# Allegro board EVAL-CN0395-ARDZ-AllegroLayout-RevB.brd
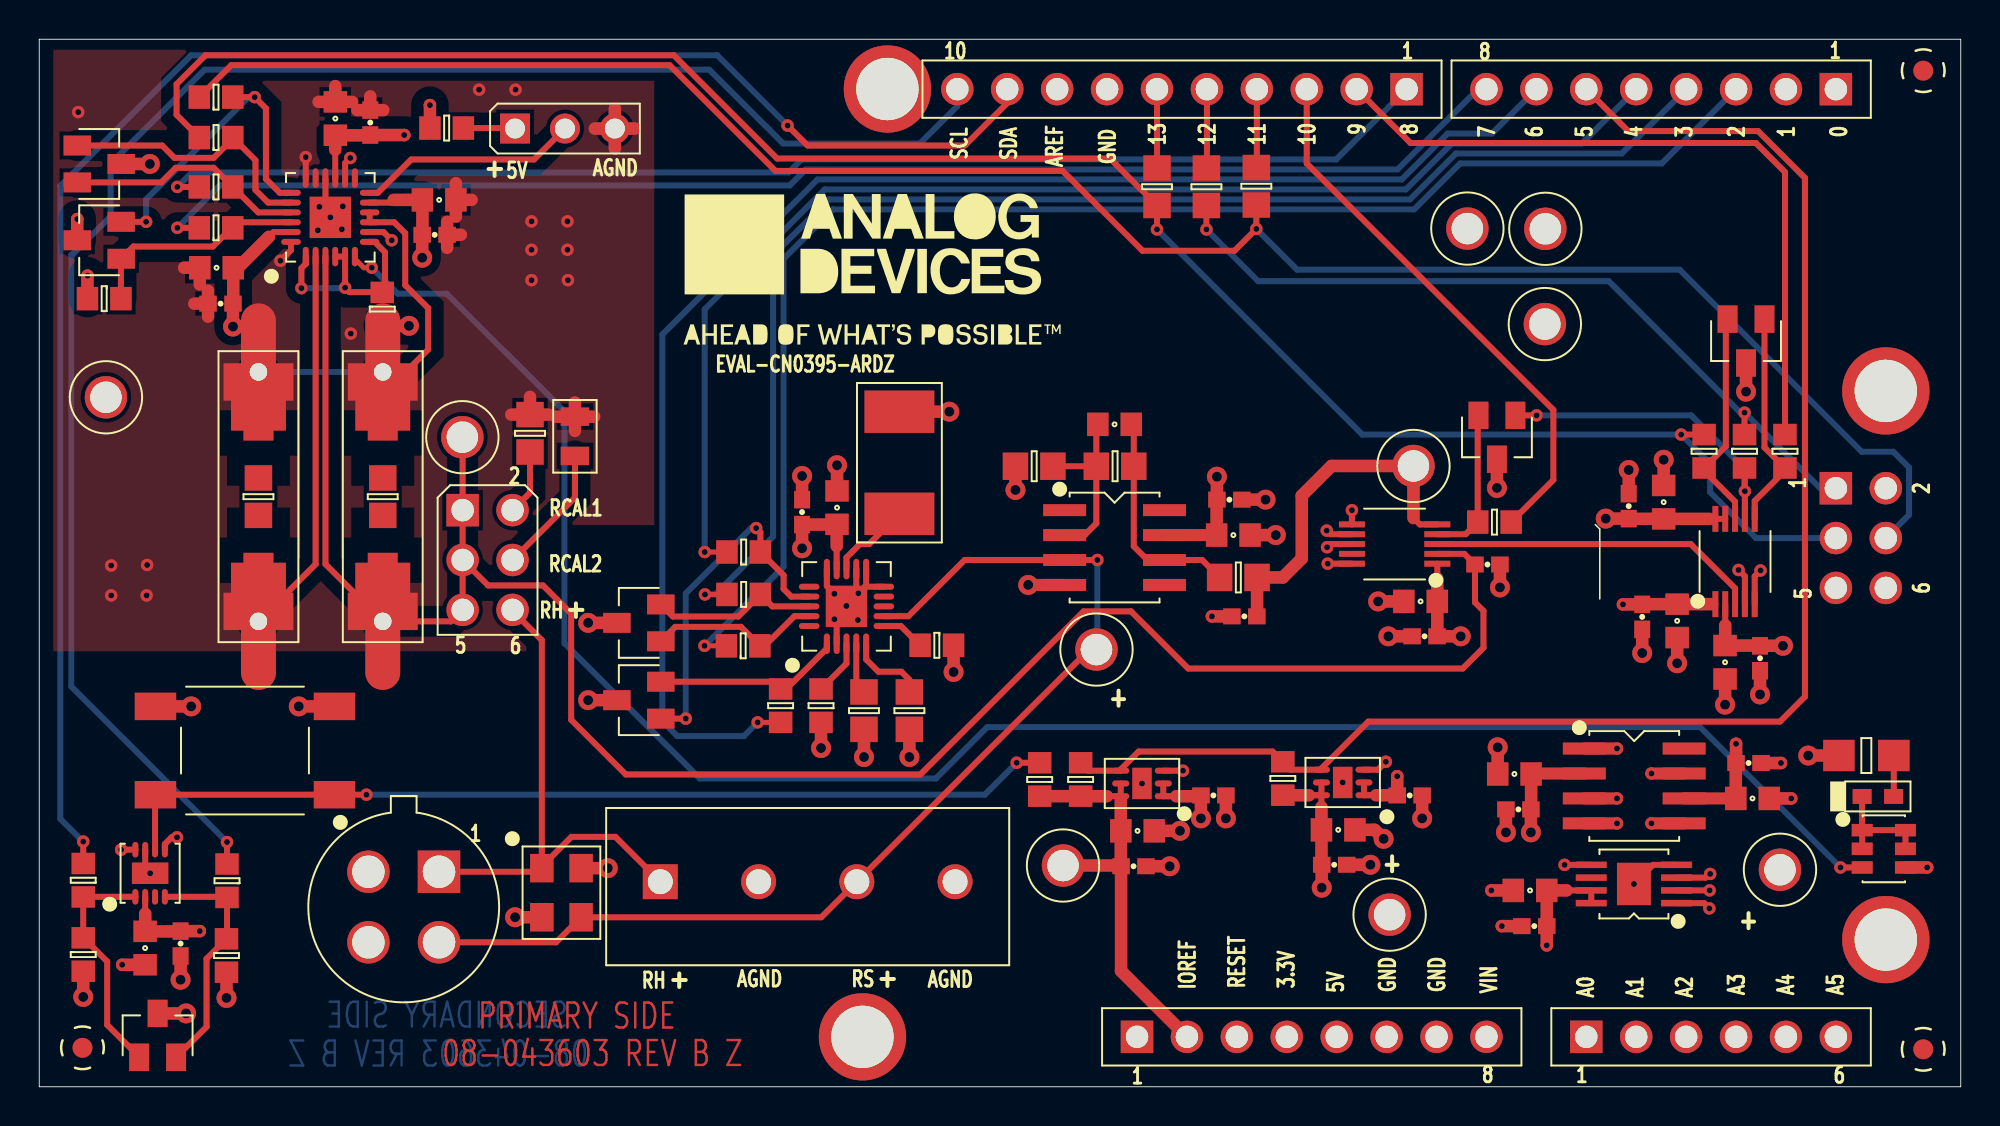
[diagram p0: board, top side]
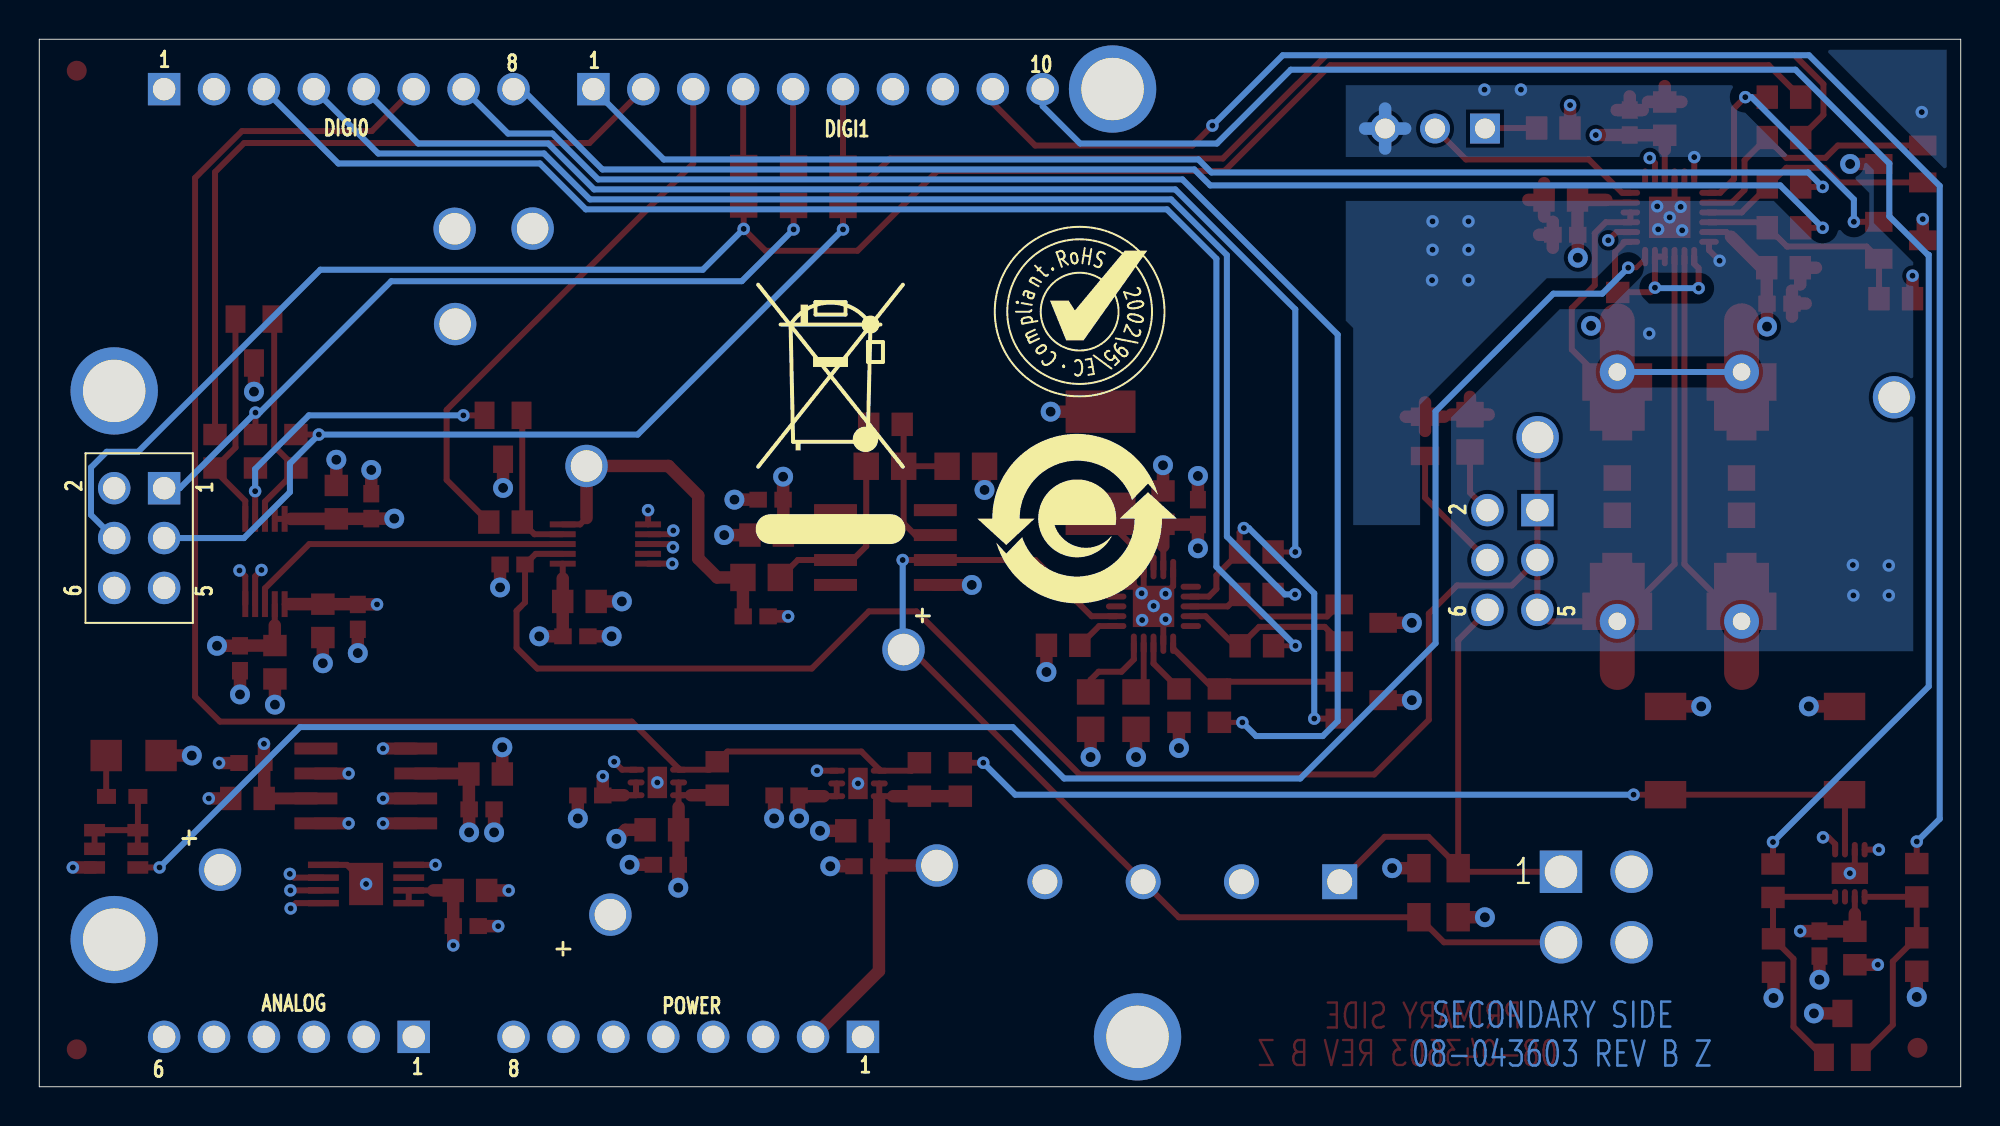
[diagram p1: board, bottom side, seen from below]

Outline 97.76 x 53.34 mm; copper layers: TOP, L2_GND, L3_PWR, BOTTOM. Coordinates in mm from the lower left corner of the outline.
Outline path: 0,53.34 0,0 97.76,0 97.76,53.34 0,53.34

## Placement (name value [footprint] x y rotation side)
A1  AD8628ARZ  [SO8]  54.71 27.46 270 top
AGND  RED  [CNLOOPTP]  76.63 43.69 0 top
C1  10uF  [C0402]  55.68 11.23 180 top
C2  10uF  [C0402]  65.89 11.3 180 top
C3  0.1uF  [C0603]  55.88 13.03 180 top
C4  0.1uF  [C0603]  66.09 13.08 180 top
C5  10uF  [C0402]  76.07 8.18 0 top
C6  0.1uF  [C0603]  75.85 9.99 0 top
C7  1uF  [C0402]  59.74 14.83 180 top
C8  1uF  [C0402]  69.73 14.83 180 top
C9  0.1uF  [C0603]  75.06 15.93 0 top
C10  1uF  [C0402]  75.26 14.12 0 top
C11  0.1uF  [C0603]  87.17 14.68 180 top
C12  1uF  [C0402]  86.97 16.48 180 top
C13  10uF  [C0402]  20.12 43.38 180 top
C14  0.1uF  [C0603]  20.35 45.16 180 top
C15  10uF  [C0402]  38.81 29.26 270 top
C16  0.1uF  [C0603]  40.59 29.49 270 top
C17  10uF  [C0402]  16.84 49.1 90 top
C18  0.1uF  [C0603]  15.06 49.3 90 top
C19  10uF  [C0402]  9.22 39.88 180 top
C20  0.1uF  [C0603]  9.02 41.71 180 top
C21  10uF  [C0402]  60.55 29.9 180 top
C22  0.1uF  [C0603]  60.76 28.09 180 top
C23  0.1uF  [C0603]  54.71 33.73 0 top
C24  1000pF  [C0402]  61.32 23.95 0 top
C25  220pF  [C0402]  73.69 26.59 180 top
C26  10uF  [C0402]  70.48 22.94 0 top
C27  0.1uF  [C0603]  70.28 24.71 0 top
C28  0.1uF  [C0603]  83.34 23.72 90 top
C29  1uF  [C0402]  81.56 23.93 90 top
C30  10uF  [C0402]  87.55 21.82 90 top
C31  0.1uF  [C0603]  85.78 21.62 90 top
C32  10uF  [C0402]  80.87 29.57 90 top
C33  0.1uF  [C0603]  82.65 29.77 90 top
C34  10uF  [C0402]  7.19 7.29 90 top
C35  0.1uF  [C0603]  5.38 7.06 90 top
D1  BAT54C  [SOT23]  3.05 43.1 90 top
D2  BAT54C  [SOT23]  30.51 19.69 90 top
D3  BAT54C  [SOT23]  3.05 46.99 270 top
D4  BAT54C  [SOT23]  74.17 33.07 180 top
D5  BAT54C  [SOT23]  86.84 37.97 180 top
D6  BAT54C  [SOT23]  6.02 2.62 0 top
D7  BAT54C  [SOT23]  30.51 23.62 90 top
DS1  APT1608SRCPRV  [LED0603]  93.55 14.78 0 top
IOREF  RED  [CNLOOPTP]  52.09 11.26 0 top
M1  VOC-MF1  [MVOC-MF1]  18.54 9.15 180 top
NOREF  -  []  97.76 0 90 top
NOREF#2  -  []  -124.84 228.42 0 top
NOREF#3  -  []  0 53.34 0 top
NOREF#4  -  []  0 0.03 0 top
NOREF#5  -  []  -234.98 -254 0 top
NOREF#6  -  []  201.93 49.48 0 top
NOREF#7  -  []  -0.03 53.37 270 top
NOREF#8  -  []  -234.98 -254 0 top
NOREF#9  -  [unnamed#2]  93.95 7.49 0 top
NOREF#10  -  []  0 0.03 0 top
NOREF#11  -  [unnamed#2]  93.95 35.43 0 top
NOREF#12  -  []  97.76 0 90 top
NOREF#13  -  [unnamed#2]  95.86 1.91 0 top
NOREF#14  -  []  21.13 1.66 0 top
NOREF#15  -  [unnamed#2]  41.88 2.54 0 top
NOREF#16  -  [unnamed#2]  43.15 50.81 0 top
NOREF#17  -  []  97.82 0 0 top
NOREF#18  -  []  97.76 53.34 180 top
NOREF#19  -  []  0 53.34 0 top
NOREF#20  -  [unnamed#2]  95.86 51.74 0 top
NOREF#21  -  []  146.02 209.55 0 top
NOREF#22  -  []  -234.98 -254 0 top
NOREF#23  -  []  0 0 0 top
NOREF#24  -  []  279.7 195.43 0 top
NOREF#25  -  [unnamed#2]  2.2 1.98 0 top
NOREF#26  -  []  165.15 243.21 0 top
NOREF#27  -  []  42.4 41.62 0 top
NOREF#28  -  []  48.23 44.53 180 bottom
NOREF#29  -  []  44.83 39.47 180 bottom
NOREF#30  -  []  44.96 28.93 180 bottom
P1  22-28-4033  [CNMOLEX22-28-4033]  24.21 48.79 0 top
P2  TSW-103-08-G-D  [CNSAMTEC2X3H330LD36]  21.54 29.36 270 top
P3  SSQ-103-03-G-D  [CNSAMTECSSQ-103-XX-X-D]  91.41 30.48 270 bottom
P4  SSQ-106-03-G-S  [CNSAMTECSSQ-106-XX-X-S]  78.71 2.54 0 top
P5  SSQ-108-03-G-S  [CNSAMTECSSQ-108-XX-X-S]  55.85 2.54 0 top
P6  SSQ-110-03-G-S  [CNSAMTECSSQ-110-XX-X-S]  69.57 50.8 180 top
P7  SSQ-108-03-G-S  [CNSAMTECSSQ-108-XX-X-S]  91.41 50.8 180 top
P8  CTB5000/4  [CN1X4H394]  31.6 10.44 0 top
Q1  IRLMS2002TRPBF  [SOT23_6-3]  93.85 12.12 270 top
R1  100K  [R0603]  52.98 15.65 90 top
R2  100K  [R0603]  63.27 15.7 90 top
R3  100  [R0603]  8.99 43.74 0 top
R4  100K  [R0603]  20.73 48.82 180 top
R5  100  [R0603]  8.99 45.82 0 top
R6  100  [R0603]  35.84 25.07 0 top
R7  100  [R0603]  8.99 48.34 0 top
R8  100  [R0603]  35.84 27.23 0 top
R9  100  [R0603]  8.99 50.39 0 top
R10  8.87K  [R0603]  39.78 19.41 90 top
R11  10K  [R0603]  3.3 40.13 180 top
R12  39.2K  [R0805]  41.96 19.15 90 top
R13  110K  [R0805]  44.27 19.15 90 top
R14  2.74MEG  [R0603]  45.67 22.48 180 top
R15  100K  [R0603]  17.45 39.6 270 top
R16  33MEG  [R2512H31]  43.76 31.78 270 top
R17  8.25  [R0805]  11.15 30.05 90 top
R17_SPACER  TBD_SPACER_500_D37  [R_SPACER_500_D37]  11.15 23.7 90 top
R18  5K  [R0805]  50.62 31.6 0 top
R19  8.25  [R0805]  17.48 30.05 270 top
R19_SPACER  TBD_SPACER_500_D37  [R_SPACER_500_D37]  17.48 23.7 90 top
R20  5K  [R0805]  54.74 31.6 0 top
R21  20  [R0805]  61.01 25.93 0 top
R22  71.5  [R0805]  24.97 33.27 90 top
R23  10  [R0805H20]  27.25 33.12 90 top
R24  100  [R0603]  74.04 28.75 180 top
R25  100  [R0603]  86.77 32.36 270 top
R26  37.4  [R1206]  92.96 16.87 180 top
R27  100  [R0603]  84.71 32.36 270 top
R28  100  [R0603]  88.82 32.36 270 top
R29  10K  [R0603]  2.24 6.73 270 top
R30  10K  [R0603]  9.53 6.68 270 top
R31  100  [R0603]  2.24 10.52 90 top
R32  100  [R0603]  9.55 10.49 90 top
R33  0  [R0805]  61.93 45.85 90 top
R34  0  [R0805]  59.39 45.83 90 top
R35  0  [R0805]  56.87 45.83 90 top
R36  10K  [R0603]  50.9 15.65 90 top
R37  100  [R0603]  35.81 22.45 0 top
R38  100  [R0603]  37.72 19.41 90 top
RS+  RED  [CNLOOPTP]  53.79 22.26 0 top
S2  FSM2JSMA  [SWSMSQ236H185]  10.46 17.12 90 top
TP2  RED  [CNLOOPTP]  3.39 35.11 270 top
U1  ADN8810ACPZ  [QFN24_4X4_PAD2_1X2_1]  14.81 44.27 0 top
U2  -  [TGS8100]  26.57 9.88 270 top
U3  ADP196ACPZN  [DFN6_2X2_PAD1_6X1]  56.11 15.44 90 top
U4  ADP196ACPZN  [DFN6_2X2_PAD1_6X1]  66.32 15.49 90 top
U5  ADP124ARHZ-2.5  [MSOP8_PAD2_16X1_73]  81.14 10.32 90 top
U6  ADR4540BRZ  [SO8]  81.15 15.32 270 top
U7  ADG758BCPZ  [QFN20_4X4_PAD2_1X2_1]  41.07 24.46 0 top
U8  ADG884BRMZ  [RM10]  68.96 27.64 90 top
U9  AD7988-1BRMZ  [RM10]  86.28 26.75 0 top
U10  SHT30-DIS-B2.5KS  [DFN8_2_5X2_5_PAD1_8X1_1]  5.64 10.87 0 top
UNK4.096V  RED  [CNLOOPTP]  76.61 38.84 0 top
UNK5V  RED  [CNLOOPTP]  72.66 43.7 0 top
UNK+2.5V  RED  [CNLOOPTP]  88.57 11.05 0 top
UNK+5V_ARD  RED  [CNLOOPTP]  68.71 8.76 0 top
VH  RED  [CNLOOPTP]  21.53 33.08 270 top
VRS  RED  [CNLOOPTP]  69.92 31.61 0 top

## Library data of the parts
A1 = AD8628: Tolerance: N/A; User Part Number: UPN; alternate symbols: (); part number: AD8628_SM-AD8628ARZ,E018085,SO8; tolerance: N/A
AGND IOREF RS+ TP2 UNK4.096V UNK5V UNK+2.5V UNK+5V_ARD VH VRS = CNTP1P: User Part Number: UPN; Tolerance: N/A; alternate symbols: (); part number: CNTP1P_TH-RED,E000947,CNLOOPTP; tolerance: N/A
C1 C2 C5 C13 C15 C17 C19 C21 C26 C30 C32 C34 = CAP: Tolerance: 20; User Part Number: UPN; alternate symbols: (); part number: CAP_SM-10UF,6.3V,20,E020966,C0402; tolerance: 20
C3 C4 C6 C9 C11 C14 C16 C18 C20 C22 C23 C27 C28 C31 C33 C35 = CAP: Tolerance: 10; User Part Number: UPN; alternate symbols: (); part number: CAP_SM-0.1UF,16V,10,E015036,C0603; tolerance: 10
C7 C8 C10 C12 C29 = CAP: Tolerance: 10; User Part Number: UPN; alternate symbols: (); part number: CAP_SM-1UF,6.3V,10,E007449,C0402; tolerance: 10
C24 = CAP: Tolerance: 5; User Part Number: UPN; alternate symbols: (); part number: CAP_SM-1000PF,50V,5,E012419,C0402; tolerance: 5
C25 = CAP: Tolerance: 5; User Part Number: UPN; alternate symbols: (); part number: CAP_SM-220PF,50V,5,E012615,C0402; tolerance: 5
D1-D7 = DIOSCHOTTKY3P_V10: User Part Number: UPN; Tolerance: N/A; alternate symbols: (); part number: DIOSCHOTTKY3P_V10_SM-BAT54C,30V,N/A,E021001,SOT23; tolerance: N/A
DS1 = DIOLED: Tolerance: N/A; User Part Number: UPN; alternate symbols: (); part number: DIOLED_SM-APT1608SRCPRV,N/A,N/A,E018073,LED0603; tolerance: N/A
M1 = MOD_VOC_MF1: User Part Number: UPN; Tolerance: N/A; alternate symbols: MVOC-MF1_SKTLD55; part number: MOD_VOC_MF1_TH-VOC-MF1,E026030,MVOC-MF1; tolerance: N/A
P1 = CN3P: User Part Number: UPN; Tolerance: N/A; alternate symbols: (); part number: CN3P_TH-22-28-4033,E005952,CNMOLEX22-28-4033; tolerance: N/A
P2 = CN6P_ODD_EVEN: Tolerance: N/A; User Part Number: UPN; alternate symbols: (); part number: CN6P_ODD_EVEN_TH-TSW-103-08-G-D,E006383,CNSAMTEC2X3H330LD36; tolerance: N/A
P3 = CN6P: User Part Number: UPN; Tolerance: N/A; alternate symbols: (); part number: CN6P_TH-SSQ-103-03-G-D,E020488,CNSAMTECSSQ-103-XX-X-D; tolerance: N/A
P4 = CN6P: User Part Number: UPN; Tolerance: N/A; alternate symbols: (); part number: CN6P_TH-SSQ-106-03-G-S,E020477,CNSAMTECSSQ-106-XX-X-S; tolerance: N/A
P5 P7 = CN8P_A: User Part Number: UPN; Tolerance: N/A; alternate symbols: (); part number: CN8P_A_TH-SSQ-108-03-G-S,E020478,CNSAMTECSSQ-108-XX-X-S; tolerance: N/A
P6 = CN10P: User Part Number: UPN; Tolerance: N/A; alternate symbols: (); part number: CN10P_TH-SSQ-110-03-G-S,E020479,CNSAMTECSSQ-110-XX-X-S; tolerance: N/A
P8 = CN4P: Tolerance: N/A; User Part Number: UPN; alternate symbols: (); part number: CN4P_TH-CTB5000/4,E015992,CN1X4H394; tolerance: N/A
Q1 = TRANNMOSFET_V17: User Part Number: UPN; Tolerance: N/A; alternate symbols: (); part number: TRANNMOSFET_V17_SM-IRLMS2002TRPBF,E018862,SOT23_6-3; tolerance: N/A
R1 R2 R4 R15 = RES: Tolerance: 1; User Part Number: UPN; alternate symbols: (); part number: RES_SM-100K,E010279,1/10W,1,R0603; tolerance: 1
R3 R5-R9 R24 R25 R27 R28 R31 R32 R37 R38 = RES: Tolerance: 1; User Part Number: UPN; alternate symbols: (); part number: RES_SM-100,E003668,1/10W,1,R0603; tolerance: 1
R10 = RES: Tolerance: 0.1; User Part Number: UPN; alternate symbols: (); part number: RES_SM-8.87K,E021125,1/10W,0.1,R0603; tolerance: 0.1
R11 R36 = RES: Tolerance: 1; User Part Number: UPN; alternate symbols: (); part number: RES_SM-10K,E003671,1/10W,1,R0603; tolerance: 1
R12 = RES: Tolerance: 0.1; User Part Number: UPN; alternate symbols: (); part number: RES_SM-39.2K,E020454,1/8W,0.1,R0805; tolerance: 0.1
R13 = RES: Tolerance: 0.1; User Part Number: UPN; alternate symbols: (); part number: RES_SM-110K,E010949,1/8W,0.1,R0805; tolerance: 0.1
R14 = RES: Tolerance: 1; User Part Number: UPN; alternate symbols: (); part number: RES_SM-2.74MEG,E028525,1/10W,1,R0603; tolerance: 1
R16 = RES: User Part Number: UPN; Tolerance: 1; alternate symbols: (); part number: RES_SM-33MEG,E028402,1W,1,R2512H31; tolerance: 1
R17 R19 = RES: Tolerance: 0.1; User Part Number: UPN; alternate symbols: (); part number: RES_SM-8.25,E026824,1/10W,0.1,R0805; tolerance: 0.1
R17_SPACER R19_SPACER = RES: User Part Number: UPN; alternate symbols: (); part number: RES_TH-TBD_SPACER_500_D37,E018836,TBD_SPACER_500_D37,TBD_SPACER_500_D37,R_SPACER_500_D37
R18 R20 = RES: Tolerance: 0.1; User Part Number: UPN; alternate symbols: (); part number: RES_SM-5K,E014315,1/5W,0.1,R0805; tolerance: 0.1
R21 = RES: Tolerance: 1; User Part Number: UPN; alternate symbols: (); part number: RES_SM-20,E003563,1/8W,1,R0805; tolerance: 1
R22 = RES: Tolerance: 0.1; User Part Number: UPN; alternate symbols: (); part number: RES_SM-71.5,E026034,1/4W,0.1,R0805; tolerance: 0.1
R23 = RES: Tolerance: 0.1; User Part Number: UPN; alternate symbols: (); part number: RES_SM-10,E026825,1W,0.1,R0805H20; tolerance: 0.1
R26 = RES: Tolerance: 1; User Part Number: UPN; alternate symbols: (); part number: RES_SM-37.4,E003269,1/4W,1,R1206; tolerance: 1
R29 R30 = RES: Tolerance: 1; User Part Number: UPN; alternate symbols: (); part number: RES_SM-10K,E015126,1/4W,1,R0603; tolerance: 1
R33-R35 = RES: Tolerance: N/A; User Part Number: UPN; alternate symbols: (); part number: RES_SM-0,E004152,1/10W,N/A,R0805; tolerance: N/A
S2 = SWSPST4PIN_B: User Part Number: UPN; Tolerance: N/A; alternate symbols: (); part number: SWSPST4PIN_B_SM-FSM2JSMA,E016530,SWSMSQ236H185; tolerance: N/A
U1 = ADN8810: Tolerance: N/A; User Part Number: UPN; alternate symbols: (); part number: ADN8810_SM-ADN8810ACPZ,E025853,QFN24_4X4_PAD2_1X2_1; tolerance: N/A
U2 = ICTGS8100: User Part Number: UPN; Tolerance: N/A; alternate symbols: (); part number: ICTGS8100_SM-TGS8100,E025852,TGS8100; tolerance: N/A
U3 U4 = ADP196_V2: User Part Number: UPN; Tolerance: N/A; alternate symbols: (); part number: ADP196_V2_SM-ADP196ACPZN,E020439,DFN6_2X2_PAD1_6X1; tolerance: N/A
U5 = ADP124: Tolerance: N/A; User Part Number: UPN; alternate symbols: (); part number: ADP124_SM-ADP124ARHZ-2.5,E021632,MSOP8_PAD2_16X1_73; tolerance: N/A
U6 = ADR45XX: Tolerance: N/A; User Part Number: UPN; alternate symbols: (); part number: ADR45XX_SM-ADR4540BRZ,E017544,SO8; tolerance: N/A
U7 = ADG758: User Part Number: UPN; Tolerance: N/A; alternate symbols: (); part number: ADG758_SM-ADG758BCPZ,E021726,QFN20_4X4_PAD2_1X2_1; tolerance: N/A
U8 = ADG884_V2: Tolerance: N/A; User Part Number: UPN; alternate symbols: (); part number: ADG884_V2_SM-ADG884BRMZ,E014585,RM10; tolerance: N/A
U9 = AD7988: Tolerance: N/A; User Part Number: UPN; alternate symbols: (); part number: AD7988_SM-AD7988-1BRMZ,E024959,RM10; tolerance: N/A
U10 = ICSHT3X: User Part Number: UPN; Tolerance: N/A; alternate symbols: (); part number: ICSHT3X_SM-SHT30-DIS-B2.5KS,E025987,DFN8_2_5X2_5_PAD1_8X1_1; tolerance: N/A

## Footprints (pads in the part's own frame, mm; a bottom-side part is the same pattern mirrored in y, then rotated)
C0402
  rect 0.889x0.813 smd: 1(-0.635,0) 2(0.635,0)
C0603
  rect 1.092x1.194 smd: 1(-0.851,0) 2(0.851,0)
CN1X4H394
  rect 1.778x1.778 hole 1.27: 1(0,0)
  round 1.778 hole 1.27: 2(5,0) 3(10,0) 4(15,0)
CNLOOPTP
  round 2.159 hole 1.6: 1(0,0)
CNMOLEX22-28-4033
  rect 1.524x1.524 hole 1.016: 1(0,0)
  round 1.524 hole 1.016: 2(2.54,0) 3(5.08,0)
CNSAMTEC2X3H330LD36
  rect 1.651x1.651 hole 1.143: 1(0,0)
  round 1.651 hole 1.143: 2(0,2.54) 3(2.54,0) 4(2.54,2.54) 5(5.08,0) 6(5.08,2.54)
CNSAMTECSSQ-103-XX-X-D
  rect 1.651x1.651 hole 1.143: 1(0,0)
  round 1.651 hole 1.143: 2(0,-2.54) 3(2.54,0) 4(2.54,-2.54) 5(5.08,0) 6(5.08,-2.54)
CNSAMTECSSQ-106-XX-X-S
  rect 1.651x1.651 hole 1.143: 1(0,0)
  round 1.651 hole 1.143: 2(2.54,0) 3(5.08,0) 4(7.62,0) 5(10.16,0) 6(12.7,0)
CNSAMTECSSQ-108-XX-X-S
  rect 1.651x1.651 hole 1.143: 1(0,0)
  round 1.651 hole 1.143: 2(2.54,0) 3(5.08,0) 4(7.62,0) 5(10.16,0) 6(12.7,0) 7(15.24,0) 8(17.78,0)
CNSAMTECSSQ-110-XX-X-S
  rect 1.651x1.651 hole 1.143: 1(0,0)
  round 1.651 hole 1.143: 2(2.54,0) 3(5.08,0) 4(7.62,0) 5(10.16,0) 6(12.7,0) 7(15.24,0) 8(17.78,0) 9(20.32,0) 10(22.86,0)
DFN6_2X2_PAD1_6X1
  oval 0.305x0.864 smd: 1(-0.65,-1.082) 2(0,-1.082) 3(0.65,-1.082) 4(0.65,1.082) 5(0,1.082) 6(-0.65,1.082)
  rect 1.6x0.991 smd: PAD(0,0)
DFN8_2_5X2_5_PAD1_8X1_1
  oval 0.305x0.787 smd: 1(-0.75,-1.2) 2(-0.25,-1.2) 3(0.25,-1.2) 4(0.75,-1.2) 5(0.75,1.2) 6(0.25,1.2) 7(-0.25,1.2) 8(-0.75,1.2)
  rect 1.854x1.092 smd: PAD(0,0)
LED0603
  rect 0.965x0.762 smd: A(0.8,0) C(-0.8,0)
MSOP8_PAD2_16X1_73
  rect 0.33x1.575 smd: 1(-0.975,-2.171) 2(-0.325,-2.171) 3(0.325,-2.171) 4(0.975,-2.171) 5(0.975,2.171) 6(0.325,2.171) 7(-0.325,2.171) 8(-0.975,2.171)
  rect 2.159x1.727 smd: PAD(0,0)
MVOC-MF1
  rect 2.159x2.159 hole 1.651: 1(-1.796,-1.796)
  round 2.159 hole 1.651: 2(-1.796,1.796) 3(1.796,1.796) 4(1.796,-1.796)
QFN20_4X4_PAD2_1X2_1
  oval 0.305x1.041 smd: 1(-1,-1.9) 2(-0.5,-1.9) 3(0,-1.9) 4(0.5,-1.9) 5(1,-1.9) 11(1,1.9) 12(0.5,1.9) 13(0,1.9) 14(-0.5,1.9) 15(-1,1.9)
  oval 1.041x0.305 smd: 6(1.9,-1) 7(1.9,-0.5) 8(1.9,0) 9(1.9,0.5) 10(1.9,1) 16(-1.9,1) 17(-1.9,0.5) 18(-1.9,0) 19(-1.9,-0.5) 20(-1.9,-1)
  rect 2.108x2.108 smd: PAD(0,0)
QFN24_4X4_PAD2_1X2_1
  oval 0.305x0.991 smd: 1(-1.25,-2) 2(-0.75,-2) 3(-0.25,-2) 4(0.25,-2) 5(0.75,-2) 6(1.25,-2) 13(1.25,2) 14(0.75,2) 15(0.25,2) 16(-0.25,2) 17(-0.75,2) 18(-1.25,2)
  oval 0.991x0.305 smd: 7(2,-1.25) 8(2,-0.75) 9(2,-0.25) 10(2,0.25) 11(2,0.75) 12(2,1.25) 19(-2,1.25) 20(-2,0.75) 21(-2,0.25) 22(-2,-0.25) 23(-2,-0.75) 24(-2,-1.25)
  rect 2.108x2.108 smd: PAD(0,0)
R0603
  rect 1.092x1.194 smd: 1(-0.851,0) 2(0.851,0)
R0805
  rect 1.295x1.397 smd: 1(-0.953,0) 2(0.953,0)
R0805H20
  rect 0.94x1.448 smd: 1(-1,0) 2(1,0)
R1206
  rect 1.6x1.6 smd: 1(-1.397,0) 2(1.397,0)
R2512H31
  rect 2.159x3.556 smd: 1(-2.6,0) 2(2.6,0)
R_SPACER_500_D37
  custom 0.889x0.889 hole 0.94: 1(0,0) 2(12.7,0)
RM10
  rect 0.305x1.321 smd: 1(-1,-2.171) 2(-0.5,-2.171) 3(0,-2.171) 4(0.5,-2.171) 5(1,-2.171) 6(1,2.171) 7(0.5,2.171) 8(0,2.171) 9(-0.5,2.171) 10(-1,2.171)
SO8
  rect 0.61x2.184 smd: 1(-1.905,-2.54) 2(-0.635,-2.54) 3(0.635,-2.54) 4(1.905,-2.54) 5(1.905,2.54) 6(0.635,2.54) 7(-0.635,2.54) 8(-1.905,2.54)
SOT23
  rect 1.016x1.397 smd: 1(-0.94,-1.118) 2(0.94,-1.118) 3(0,1.118)
SOT23_6-3
  rect 0.635x1.067 smd: 1(-0.95,-1.1) 2(0,-1.1) 3(0.95,-1.1) 4(0.95,1.1) 5(0,1.1) 6(-0.95,1.1)
SWSMSQ236H185
  rect 1.397x2.108 smd: 1(-2.248,-4.554) 2(-2.248,4.554) 3(2.248,-4.554) 4(2.248,4.554)
TGS8100
  rect 1.448x1.194 smd: 1(-1.25,-1) 2(1.25,-1) 3(1.25,1) 4(-1.25,1)
unnamed#2
  round 4.445 hole 3.175 unplated: (0,0)

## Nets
+2.5V: C30.2(N2) C31.2(N2) R26.2(N2) U5.1(VOUT1) U5.2(VOUT2) U5.3(VOUT_SENSE) U9.2(VDD) UNK+2.5V.1
+4.096V: C11.2(N2) C12.2(N2) C28.2(N2) C29.2(N2) R10.1(N1) R12.1(N1) R13.1(N1) R14.1(N1) R16.1(N1) U1.14(VREF) U6.6(VOUT) U9.1(REF) UNK4.096V.1
+5V: A1.7(V+) C5.2(N2) C6.2(N2) C8.2(N2) C9.2(N2) C10.2(N2) C13.2(N2) C14.2(N2) C15.2(N2) C16.2(N2) C17.1(N1) C18.1(N1) C21.2(N2) C22.2(N2) C26.2(N2) C27.2(N2) D2.3(N3) D4.3(N3) D5.3(N3) D7.3(N3) R4.2(N2) U1.8(PVDD_1) U1.11(PVDD_2) U1.15(AVDD) U4.1(VOUT1) U4.2(VOUT2) U5.5(EN) U5.7(VIN1) U5.8(VIN2) U6.2(VIN) U7.14(VDD) U8.1(VDD) UNK5V.1
+5V_ARD: C2.2(N2) C4.2(N2) P5.5(N5) R2.1(N1) U4.5(VIN2) U4.6(VIN1) UNK+5V_ARD.1
AGND: A1.4(V-) AGND.1(N1) C1.1(N1) C2.1(N1) C3.1(N1) C4.1(N1) C5.1(N1) C6.1(N1) C7.1(N1) C8.1(N1) C9.1(N1) C10.1(N1) C11.1(N1) C12.1(N1) C13.1(N1) C14.1(N1) C15.1(N1) C16.1(N1) C17.2(N2) C18.2(N2) C19.2(N2) C20.2(N2) C21.1(N1) C22.1(N1) C24.1(N1) C25.1(N1) C26.1(N1) C27.1(N1) C28.1(N1) C29.1(N1) C30.1(N1) C31.1(N1) C32.2(N2) C33.2(N2) C34.1(N1) C35.1(N1) M1.3(HE_2) M1.4(DE_2) P1.3(N3) P3.6(N6) P5.6(N6) P5.7(N7) P6.7(N7) P8.2(N2) P8.4(N4) Q1.4(S) R18.1(N1) R22.2(N2) R23.2(N2) S2.3(N3) S2.4(N4) U1.16(AVSS) U1.18(DVSS) U1.24(DGND) U1.PAD U2.2(SENSOR_ELECTRODE(-)) U2.4(HEATER2) U3.3(GND) U3.PAD U4.3(GND) U4.PAD U5.4(GND) U5.PAD(EP) U6.1(NC1) U6.3(NC2) U6.4(GND) U6.5(NC3) U6.7(NC4) U7.2(VSS) U7.10(S8) U7.11(S7) U7.12(S6) U7.15(GND) U7.PAD U8.6(GND) U8.7(S2B) U8.8(IN2) U8.10(S2A) U9.4(IN-) U9.5(GND) U10.7(R) U10.8(VSS) U10.PAD
A0: P7.3(N3) R37.1(N1)
A1: P7.4(N4) R6.1(N1)
A2: P7.5(N5) R8.1(N1)
CNV: P6.2(N2) R28.1(N1)
CS_N_ARD: P6.1(N1) R5.1(N1)
FAULT: Q1.3(G) U1.6(FAULT)
IN1: P6.3(N3) R24.1(N1)
IO5: P7.6(N6) R1.2(N2) R2.2(N2) U3.4(EN) U4.4(EN)
IO6: P7.7(N7) R38.1(N1)
IO7: P7.8(N8) R3.1(N1)
IOREF: C1.2(N2) C3.2(N2) IOREF.1(N1) P5.2(N2) R1.1(N1) R36.1(N1) U3.5(VIN2) U3.6(VIN1)
MISO_ARD: P3.1(N1) R25.1(N1) R34.1(N1)
MOSI_ARD: P3.4(N4) R9.1(N1) R33.1(N1)
RESET: D1.1(N1) R3.2(N2) R11.1(N1) U1.22(RESET*)
RH+: M1.1(HE_1) P2.6(N6) P8.1(N1) U2.1(HEATER1)
RS+: A1.3(+IN) M1.2(DE_1) P8.3(N3) RS+.1(N1) U2.3(SENSOR_ELECTRODE(+)) U7.7(D)
RSN: R17.1(N1) R17_SPACER.1(N1) U1.2(RSN)
SCL_ARD: P6.10(N10) R32.2(N2)
SCLK_ARD: P3.3(N3) R7.1(N1) R27.1(N1) R35.1(N1)
SDA_ARD: P6.9(N9) R31.2(N2)
SDO: D4.1(N1) R25.2(N2) U9.7(SDO)
UNNAMED_4_AD8628_I22_: A1.2(-IN) C23.1(N1) R18.2(N2) R20.1(N1)
UNNAMED_4_AD8628_I22_OUT: A1.6(OUT) C23.2(N2) R20.2(N2) R21.1(N1)
UNNAMED_4_ADG758_I12_A1: D7.2(N2) R6.2(N2) U7.18(A1)
UNNAMED_4_ADG758_I12_A2: D2.1(N1) R8.2(N2) U7.17(A2)
UNNAMED_4_ADG758_I12_EN: D2.2(N2) R38.2(N2) U7.1(EN)
UNNAMED_4_ADG758_I12_S1: R10.2(N2) U7.3(S1)
UNNAMED_4_ADG758_I12_S2: R12.2(N2) U7.4(S2)
UNNAMED_4_ADG758_I12_S3: R13.2(N2) U7.5(S3)
UNNAMED_4_ADG758_I12_S4: R14.2(N2) U7.6(S4)
UNNAMED_4_ADG758_I12_S5: R16.2(N2) U7.13(S5)
UNNAMED_4_ADN8810_I1_ADDR0: R15.1(N1) U1.1(ADDR2) U1.4(ADDR1) U1.5(ADDR0) U1.7(SB*)
UNNAMED_4_ADN8810_I1_CS: D3.2(N2) R5.2(N2) U1.21(CS*)
UNNAMED_4_ADN8810_I1_ENCOMP: P1.2(N2) U1.12(ENCOMP)
UNNAMED_4_ADN8810_I1_IOUT1: R17.2(N2) R17_SPACER.2(N2) R19.1(N1) R19_SPACER.2(N2) U1.9(IOUT_1) U1.10(IOUT_2)
UNNAMED_4_ADN8810_I1_SCLK: D3.1(N1) R7.2(N2) U1.20(SCLK)
UNNAMED_4_ADN8810_I1_SDI: D1.2(N2) R9.2(N2) U1.19(SDI)
UNNAMED_4_CN3P_I51_N1: P1.1(N1) R4.1(N1)
UNNAMED_4_CN6PODDEVEN_I59_N2: P2.2(N2) R22.1(N1)
UNNAMED_4_CN6PODDEVEN_I59_N4: P2.4(N4) R23.1(N1)
UNNAMED_4_DIOSCHOTTKY3PV10_I80_: D7.1(N1) R37.2(N2) U7.19(A0)
UNNAMED_5_AD7988_I3_CNV: D5.1(N1) R28.2(N2) U9.6(CNV)
UNNAMED_5_AD7988_I3_IN: U8.3(D1) U9.3(IN+)
UNNAMED_5_AD7988_I3_SCK: D5.2(N2) R27.2(N2) U9.8(SCK)
UNNAMED_5_DIOLED_I70_N: DS1.C(N) Q1.1(D1) Q1.2(D2) Q1.5(D3) Q1.6(D4)
UNNAMED_5_DIOLED_I70_P: DS1.A(P) R26.1(N1)
UNNAMED_5_DIOSCHOTTKY3PV10_I6_1: D6.2(N2) R30.1(N1) R32.1(N1) U10.4(SCL)
UNNAMED_5_DIOSCHOTTKY3PV10_I60_: D4.2(N2) R24.2(N2) U8.4(IN1)
UNNAMED_5_DIOSCHOTTKY3PV10_I64_: D6.1(N1) R29.1(N1) R31.1(N1) U10.1(SDA)
UNNAMED_5_RES_I68_N2: R36.2(N2) S2.1(N1) S2.2(N2) U10.6(RESET_N)
UNNAMED_7_CN10P_I1_N4: P6.4(N4) R33.2(N2)
UNNAMED_7_CN10P_I1_N5: P6.5(N5) R34.2(N2)
UNNAMED_7_CN10P_I1_N6: P6.6(N6) R35.2(N2)
VH: C25.2(N2) P2.1(N1) P2.3(N3) P2.5(N5) R19.2(N2) R19_SPACER.1(N1) U1.3(FB) U8.2(S1A) VH.1(N1)
VIO: C7.2(N2) C19.1(N1) C20.1(N1) C32.1(N1) C33.1(N1) C34.2(N2) C35.2(N2) D1.3(N3) D3.3(N3) D6.3(N3) R11.2(N2) R15.2(N2) R29.2(N2) R30.2(N2) TP2.1(N1) U1.23(DVDD) U3.1(VOUT1) U3.2(VOUT2) U9.9(SDI) U9.10(VIO) U10.2(ADDR) U10.5(VDD)
VRS: C24.2(N2) R21.2(N2) U8.5(S1B) VRS.1(N1)

Pads without a net: A1 1 5 8; P3 2 5; P4 1 2 3 4 5 6; P5 1 3 4 8; P6 8; P7 1 2; U1 13 17; U5 6; U6 8; U7 8 9 16 20; U8 9; U10 3

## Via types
v1: diameter 0.635, hole 0.305, TOP to BOTTOM, 94 vias
v2: diameter 1.016, hole 0.508, TOP to BOTTOM, 53 vias

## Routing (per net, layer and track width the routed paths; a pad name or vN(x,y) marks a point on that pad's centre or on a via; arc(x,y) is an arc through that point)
+2.5V: length 17.2
  TOP w0.305: U5.3 84.79,10.65 84.81,10.67 84.85,10.67 v1(85.02,10.84) ; v1(84.98,9.08) 84.71,9.35 U5.1 ; U5.2 v1(84.99,10) ; 85.78,23.5 U9.2
  TOP w0.635: v2(88.72,22.45) C30.2 87.54,22.47 C31.2 85.78,22.47 85.78,23.5 ; R26.2 v2(90,16.87)
  L3_PWR w0.635: UNK+2.5V.1 88.57,12.38 ; UNK+2.5V.1 88.57,9.71 ; UNK+2.5V.1 87.24,11.05 ; UNK+2.5V.1 89.9,11.05
+4.096V: length 24.6
  TOP w0.305: U1.14 15.56,47.03 v1(15.82,47.29) ; 85.06,24.58 U9.1
  TOP w0.61: U6.6 C11.2
  TOP w0.635: C11.2 86.32,16.47 86.33,16.48 v1(86.33,17.46) ; R10.1 v2(39.78,17.25) ; R16.1 v2(46.3,34.38) ; 85.06,24.58 C28.2 81.57,24.57 C29.2 v1(80.58,24.56) ; R14.1 v2(46.52,21.12) ; R13.1 v2(44.27,16.79) ; R12.1 v2(41.96,16.79)
  L3_PWR w0.635: UNK4.096V.1 76.61,40.17 ; UNK4.096V.1 77.94,38.84 ; UNK4.096V.1 76.61,37.5 ; UNK4.096V.1 75.27,38.84
+5V: length 56.9
  TOP w0.305: U5.5 v1(77.61,11.3) ; 15.06,47.71 U1.15 ; 68.02,14.84 U4.1 U4.2 ; 18.03,45.16 17.89,45.02 U1.11 ; U5.8 U5.7 77.72,10 ; U1.8 17.51,43.52 v1(17.93,43.1) ; 71.13,25.88 U8.1 ; U7.14 40.57,27.53
  TOP w0.61: A1.7 C22.2 ; C9.2 75.93,15.95 U6.2
  TOP w0.635: v2(72.33,22.94) C26.2 71.13,22.95 C27.2 71.13,24.71 71.13,25.88 ; C22.2 59.91,29.88 C21.2 v2(59.92,31.06) ; 15.06,47.71 15.06,48.45 C18.1 16.83,48.45 C17.1 v1(18.57,48.46) ; R4.2 v1(19.88,49.99) ; C9.2 75.91,14.14 C10.2 v2(75.9,12.95) ; D2.3 v2(27.93,19.69) ; v1(76.7,7.2) C5.2 C6.2 76.71,10 77.72,10 ; 68.02,14.84 69.08,14.84 C8.2 v1(69.09,15.81) ; D5.3 v2(86.84,35.39) ; 40.58,28.63 C16.2 ; 40.58,28.63 C15.2 v2(38.81,27.42) ; 40.58,28.63 40.57,28.62 40.57,27.53 ; D7.3 v2(27.93,23.62) ; D4.3 v2(74.17,30.49) ; v2(19.48,42.21) C13.2 19.49,43.4 C14.2 18.03,45.16
  L3_PWR w0.635: 71.33,43.7 UNK5V.1 ; UNK5V.1 72.66,45.03 ; UNK5V.1 74,43.7 ; UNK5V.1 72.66,42.37
+5V_ARD: length 17
  TOP w0.305: U4.5 U4.6 ; U4.6 65.24,14.24 ; U4.6 64.6,14.84
  TOP w0.635: v2(65.25,10.13) C2.2 65.24,11.32 C4.2 65.24,13.08 65.24,14.24 ; 64.6,14.84 63.27,14.84 R2.1
  L3_PWR w0.635: UNK+5V_ARD.1 70.04,8.76 ; UNK+5V_ARD.1 68.71,10.1 ; UNK+5V_ARD.1 67.37,8.76 ; UNK+5V_ARD.1 68.71,7.43 ; P5.5 67.09,2.54 ; P5.5 66.01,3.62 ; P5.5 64.93,2.54 ; P5.5 66.01,1.46
AGND: length 152
  TOP w0.305: U7.12 41.57,25.23 v1(41.68,25.13) 42.01,25.46 ; U1.24 12.81,42.6 v1(12.27,42.06) ; U10.8 v1(4.16,12.07) ; U9.5 87.28,25.99 v1(87.58,26.29) ; v1(65.52,27.47) 65.69,27.64 U8.8 ; v1(81.14,10.32) 82.11,11.3 U5.4 ; U10.7 5.39,11.12 v1(5.64,10.87) ; 42.01,25.46 U7.10 ; 42.01,25.46 42.07,25.52 U7.11 ; U4.3 68.11,16.14 v1(68.52,16.55) ; U7.15 40.07,25.49 40.46,25.11 v1(40.46,25.1) ; U8.6 v1(66.79,29.36) ; v1(65.51,28.32) 65.69,28.14 U8.7 ; U8.10 v1(65.56,26.64) ; v1(14.25,44.81) 14.56,45.11 U1.16 ; v1(40.46,23.81) 40.57,23.69 U7.2 ; U3.3 v1(58.19,16.09) ; U1.18 v1(13.56,47.34) ; U9.4 86.78,25.99 v1(86.46,26.31)
  TOP w0.61: A1.4 v2(50.32,25.55) ; U6.1 v1(80.28,17.22) ; U6.3 v1(80.28,14.68) ; U6.7 v1(82.03,15.95) ; U6.5 v1(82.03,13.41) ; U6.4 v1(80.28,13.41)
  TOP w0.635: 29.29,47.78 P1.3 ; P1.3 30.3,48.79 ; P1.3 29.29,49.81 ; P1.3 28.27,48.79 ; C27.1 v2(68.12,24.71) ; R23.2 27.25,34.85 ; R23.2 28.23,34.12 ; R23.2 27.25,33.4 ; R23.2 26.28,34.12 ; C26.1 v2(68.64,22.94) ; C13.1 20.75,44.04 ; C13.1 21.45,43.38 ; C13.1 20.75,42.72 ; C33.2 v2(82.65,31.93) ; C17.2 16.84,50.43 ; C17.2 17.5,49.73 ; C17.2 16.18,49.73 ; C2.1 v2(67.73,11.3) ; 24.02,34.23 R22.2 ; R22.2 25.92,34.23 ; R22.2 24.97,35.13 ; C16.1 v2(40.59,31.65) ; C19.2 8.59,40.54 ; C19.2 7.89,39.88 ; C19.2 8.59,39.22 ; C6.1 v1(73.88,9.99) ; 8.17,40.86 C20.2 7.37,41.71 ; 21.2,44.31 C14.1 ; C14.1 22,45.16 ; C14.1 21.2,46.01 ; S2.4 v2(7.73,19.37) ; C15.1 v2(38.81,31.1) ; C25.1 v2(74.32,25.43) ; C4.1 67.95,13.08 v2(68.4,12.62) ; C29.1 v2(81.56,22.09) ; R18.1 v2(49.67,30.39) ; C9.1 v2(74.21,17.28) ; C5.1 v1(74.42,8.18) ; C11.1 v1(89.14,14.68) ; C22.1 v2(62.92,28.09) ; C18.2 15.06,50.95 ; C18.2 14.21,50.15 ; C18.2 15.91,50.15 ; C7.1 v2(60.38,13.67) ; C34.1 v2(7.19,5.45) ; C10.1 v2(74.63,12.95) ; C1.1 v2(57.52,11.23) ; C8.1 v2(70.36,13.67) ; U2.4 v2(28.93,11.13) ; C32.2 v2(80.87,31.41) ; U2.2 v2(24.21,8.63) ; C28.1 v2(83.34,21.56) ; C31.1 v2(85.78,19.46) ; C24.1 v1(59.66,23.95) ; C12.1 v1(88.62,16.48) ; S2.3 v2(13.2,19.37) ; 61.19,29.9 v2(62.4,29.9) ; C35.1 v1(4.22,6.21) ; C3.1 v2(58.04,13.03) ; C30.1 v2(87.55,19.98) ; Q1.4 v1(96.06,11.17)
  L2_GND w0.635: P8.4 47.74,10.44 ; P8.4 45.45,10.44 ; P8.4 46.6,9.3 ; P8.4 46.6,11.58 ; P5.6 69.63,2.54 ; P5.6 67.47,2.54 ; P5.6 68.55,1.46 ; P5.6 68.55,3.62 ; 54.33,49.72 P6.7 ; P6.7 54.33,51.88 ; P6.7 55.41,50.8 ; P6.7 53.25,50.8 ; 71.09,1.46 P5.7 ; P5.7 72.17,2.54 ; P5.7 71.09,3.62 ; P5.7 70.01,2.54 ; 92.87,25.4 93.95,25.4 ; 93.95,25.4 95.03,25.4 ; 93.95,25.4 93.95,24.32 ; 93.95,25.4 93.95,26.48 ; P1.3 29.29,49.81 ; P1.3 28.27,48.79 ; P1.3 30.3,48.79 ; P1.3 29.29,47.78 ; M1.4 16.75,12.28 ; M1.4 16.75,9.61 ; M1.4 15.41,10.95 ; M1.4 18.08,10.95 ; P8.2 36.6,11.58 ; P8.2 35.45,10.44 ; P8.2 37.74,10.44 ; P8.2 36.6,9.3 ; 76.63,42.35 AGND.1 ; AGND.1 75.3,43.69 ; AGND.1 77.97,43.69 ; AGND.1 76.63,45.02 ; 15.41,7.35 M1.3 ; M1.3 16.75,8.69 ; M1.3 18.08,7.35 ; M1.3 16.75,6.02
  BOTTOM w0.635: P1.3 30.3,48.79 ; P1.3 28.27,48.79 ; P1.3 29.29,47.78 ; P1.3 29.29,49.81
  vias: v1(1.98,49.63) v1(3.66,26.54) v1(3.66,25.02) v1(5.49,26.57) v1(5.46,25.02) v1(14.17,43.61) v1(14.81,44.27) v1(15.39,43.66) v1(15.44,44.83) v1(15.85,38.35) v1(22.38,50.77) v1(24.23,50.77) v1(25.04,44.07) v1(25.04,42.62) v1(25.04,41.07) v1(26.87,44.07) v1(26.87,42.62) v1(26.9,41.07) v1(41.07,24.48) v1(41.65,23.77) v1(56.11,15.44) v1(66.32,15.49)
A0: length 74.5
  TOP w0.254: R37.1 v1(33.85,22.45)
  BOTTOM w0.305: v1(33.85,22.45) 37.87,26.48 37.87,42.16 40.39,44.68 69.96,44.68 72.29,47.02 82.55,47.02 86.33,50.8
A1: length 70.1
  TOP w0.254: R6.1 v1(33.87,25.07)
  BOTTOM w0.305: 83.79,50.8 80.52,47.52 72.08,47.52 69.75,45.19 40.18,45.19 37.34,42.35 37.34,28.02 34.39,25.07 v1(33.87,25.07)
A2: length 65.5
  TOP w0.254: R8.1 v1(33.86,27.23)
  BOTTOM w0.305: P7.5 78.49,48.03 71.87,48.03 69.53,45.69 39.96,45.69 33.86,39.59 v1(33.86,27.23)
CNV: length 36.9
  TOP w0.305: P6.2 69.77,48.06 87.34,48.06 88.82,46.58 R28.1
CS_N_ARD: length 65.7
  TOP w0.305: R5.1 v1(7.02,45.82)
  BOTTOM w0.305: v1(7.02,45.82) 7.76,46.56 38.13,46.56 38.79,47.22 65.99,47.22 P6.1
FAULT: length 98.7
  TOP w0.254: U1.6 16.06,42.16 16.51,41.71 v1(16.92,41.71)
  TOP w0.305: Q1.3 v1(91.65,11.17)
  BOTTOM w0.305: v1(16.92,41.71) 18.24,40.39 20.73,40.39 26.72,34.39 26.72,22.58 33.6,15.7 45.62,15.7 48.23,18.31 84.5,18.31 v1(91.65,11.17)
IN1: length 28.1
  TOP w0.305: R24.1 77.04,30.9 77.04,34.47 64.49,47.02 P6.3
IO5: length 78.8
  TOP w0.305: 78.71,50.8 80.85,48.67 87.45,48.67 89.84,46.28 89.84,19.86 88.57,18.59 67.62,18.59 65.24,16.21 U4.4 63.68,16.14 R2.2 62.75,17.07 55.94,17.07 55.03,16.16 U3.4 53.39,16.09 R1.2
IO6: length 76
  TOP w0.254: R38.1 v1(36.55,18.55)
  BOTTOM w0.305: v1(36.55,18.55) 35.85,17.86 32.46,17.86 31.7,18.62 31.7,38.3 39.6,46.2 69.32,46.2 71.66,48.54 73.91,48.54 P7.7
IO7: length 70.7
  TOP w0.305: R3.1 v1(7.02,43.74)
  BOTTOM w0.305: v1(7.02,43.74) 9.18,45.9 38.18,45.9 39,46.71 69.11,46.71 73.2,50.8 P7.8
IOREF: length 21.4
  TOP w0.305: 54.32,14.79 U3.6 ; U3.6 U3.5 ; U3.6 55.03,14.79 55.03,14.55
  TOP w0.635: R36.1 R1.1 52.99,14.79 54.32,14.79 ; IOREF.1 55,11.26 55.03,11.24 ; 55.03,11.24 C3.2 55.03,14.55 ; 55.03,11.24 C1.2 55.04,5.89 P5.2
MISO_ARD: length 39.8
  TOP w0.305: R25.1 v1(86.77,34.33) ; R34.1 v1(59.39,43.66)
  BOTTOM w0.305: P3.1 90.61,30.48 v1(86.77,34.33) 86.55,34.33 79.86,41.02 62.02,41.02 v1(59.39,43.66)
MOSI_ARD: length 102.4
  TOP w0.305: R33.1 v1(61.93,43.68) 60.81,42.57 56.13,42.57 52.07,46.63 37.46,46.63 32.07,52.02 9.77,52.02 R9.1
  BOTTOM w0.305: v1(61.93,43.68) 64,41.61 83.46,41.61 92.74,32.33 94.34,32.33 95.14,31.53 95.14,29.12 P3.4
RESET: length 11.4
  TOP w0.305: R11.1 4.15,42.15 D1.1 4.79,42.79 8.83,42.79 9.79,43.74 R3.2 10.13,44.02 U1.22
RH+: length 26.7
  TOP w0.305: 25.57,11.22 U2.1 25.38,10.95 M1.1 ; 25.57,11.22 25.57,22.74 24.08,24.23 P2.6 ; 25.57,11.22 27.08,12.73 29.31,12.73 P8.1
RS+: length 56.3
  TOP w0.305: M1.2 26.29,7.35 U2.3 39.79,8.63 P8.3 53.42,22.26 RS+.1 ; v1(53.84,26.82) A1.3 47.08,26.82 44.22,23.96 U7.7
  BOTTOM w0.305: RS+.1 53.84,22.31 v1(53.84,26.82)
RSN: length 19.8
  TOP w0.305: R17_SPACER.1 14.06,26.61 U1.2
SCL_ARD: length 88.1
  TOP w0.305: R32.2 v1(9.55,12.46)
  BOTTOM w0.305: P6.10 46.71,49.94 44.81,48.03 37.85,48.03 34.09,51.79 8.41,51.79 3.63,47.02 3.63,44.32 1.68,42.37 1.63,42.37 1.63,20.38 v1(9.55,12.46)
SCLK_ARD: length 101.2
  TOP w0.305: R27.1 v1(83.54,33.21) ; R7.1 6.99,49.49 6.99,51.05 8.46,52.53 32.28,52.53 37.54,47.27 54.48,47.27 R35.1 v1(56.87,43.66)
  BOTTOM w0.305: v1(56.87,43.66) 67.32,33.21 v1(83.54,33.21) 85.01,31.74 85.01,30.28 87.35,27.94 P3.3
SDA_ARD: length 89.4
  TOP w0.305: P6.9 49.25,50.09 47.09,47.93 39.09,47.93 v1(38.07,48.95) ; R31.2 v1(2.24,12.48)
  BOTTOM w0.305: v1(2.24,12.48) 2.22,12.48 1.07,13.64 1.07,45.87 7.72,52.53 34.49,52.53 v1(38.07,48.95)
SDO: length 16.5
  TOP w0.305: R25.2 86.77,30.35 v1(86.78,30.33) U9.7 ; D4.1 v1(76.19,34.19)
  BOTTOM w0.305: v1(76.19,34.19) 84.05,34.19 86.78,31.45 v1(86.78,30.33)
UNNAMED_4_AD8628_I22_: length 9.1
  TOP w0.305: A1.2 53.19,28.09 53.78,28.69 R20.1 ; C23.1 53.78,33.66 R20.1 ; R18.2 R20.1
UNNAMED_4_AD8628_I22_OUT: length 11.3
  TOP w0.305: C23.2 55.69,33.6 R20.2 55.69,27.52 56.39,26.82 A1.6 59.17,26.82 R21.1
UNNAMED_4_ADG758_I12_A1: length 8.5
  TOP w0.305: D7.2 32.24,23.95 35.57,23.95 R6.2 37.3,24.46 U7.18
UNNAMED_4_ADG758_I12_A2: length 17.7
  TOP w0.305: D2.1 v1(32.89,18.75) ; U7.17 38.26,24.96 37.87,25.35 37.87,26.05 R8.2 36.69,28.23 v1(36.47,28.45)
  BOTTOM w0.305: v1(32.89,18.75) 32.89,25.12 36.22,28.45 v1(36.47,28.45)
UNNAMED_4_ADG758_I12_EN: length 9.7
  TOP w0.305: D2.2 37.35,20.62 R38.2 38.01,20.26 40.07,22.32 U7.1
UNNAMED_4_ADG758_I12_S1: length 2.8
  TOP w0.305: R10.2 41.07,21.55 U7.3
UNNAMED_4_ADG758_I12_S2: length 2.6
  TOP w0.305: R12.2 41.57,20.49 U7.4
UNNAMED_4_ADG758_I12_S3: length 4.1
  TOP w0.305: R13.2 44.27,20.73 43.87,21.13 42.7,21.13 42.07,21.76 U7.5
UNNAMED_4_ADG758_I12_S4: length 2.3
  TOP w0.305: R14.2 43.84,23.46 U7.6
UNNAMED_4_ADG758_I12_S5: length 4.2
  TOP w0.305: U7.13 41.07,26.95 41.76,27.64 42.22,27.64 R16.2
UNNAMED_4_ADN8810_I1_ADDR0: length 11.1
  TOP w0.305: U1.7 17.06,43.02 17.59,42.49 17.59,40.59 R15.1 17.44,40.46 15.79,40.46 v1(15.56,40.69) U1.5 U1.4 ; U1.1 13.56,41.9 13.34,41.68 v1(13.34,40.67)
  BOTTOM w0.305: v1(13.34,40.67) 15.53,40.67 v1(15.56,40.69)
UNNAMED_4_ADN8810_I1_CS: length 12.1
  TOP w0.305: U1.21 11.14,44.52 R5.2 8.87,46.79 6.94,46.79 6.2,46.05 D3.2
UNNAMED_4_ADN8810_I1_ENCOMP: length 11.3
  TOP w0.305: P1.2 25.17,47.22 18.92,47.22 17.23,45.52 U1.12
UNNAMED_4_ADN8810_I1_IOUT1: length 18.1
  TOP w0.305: U1.10 U1.9 18.06,44.02 18.62,43.46 18.62,40.82 19.79,39.65 19.79,37.54 18.64,36.4 R19_SPACER.2
  BOTTOM w0.305: R17_SPACER.2 R19_SPACER.2
UNNAMED_4_ADN8810_I1_SCLK: length 13.9
  TOP w0.305: D3.1 6.25,47.93 6.88,47.3 8.87,47.3 9.84,48.27 R7.2 11,47.18 11,45.67 11.65,45.02 U1.20
UNNAMED_4_ADN8810_I1_SDI: length 17.2
  TOP w0.305: R9.2 v1(10.96,50.39) 11.53,49.82 11.53,46.23 12.24,45.52 U1.19 ; D1.2 v1(5.44,44.04)
  BOTTOM w0.305: v1(5.44,44.04) 5.44,45.19 10.64,50.39 v1(10.96,50.39)
UNNAMED_4_CN3P_I51_N1: length 2.6
  TOP w0.305: P1.1 24.18,48.82 R4.1
UNNAMED_4_CN6PODDEVEN_I59_N2: length 3.3
  TOP w0.305: P2.2 24.97,30.25 R22.1
UNNAMED_4_CN6PODDEVEN_I59_N4: length 6.6
  TOP w0.305: R23.1 27.25,30 P2.4
UNNAMED_4_DIOSCHOTTKY3PV10_I80_: length 8.9
  TOP w0.305: D7.1 32.36,23.42 35.7,23.42 R37.2 36.91,22.45 38.42,23.96 U7.19
UNNAMED_5_AD7988_I3_CNV: length 11.2
  TOP w0.305: D5.1 87.78,32.55 R28.2 88.82,31.37 87.28,29.83 U9.6
UNNAMED_5_AD7988_I3_IN: length 16.9
  TOP w0.305: U9.3 86.28,25.38 84.03,27.64 U8.3
UNNAMED_5_AD7988_I3_SCK: length 11.3
  TOP w0.305: D5.2 85.81,39 85.81,32.61 R27.2 84.71,31.37 86.28,29.79 U9.8
UNNAMED_5_DIOLED_I70_N: length 5.8
  TOP w0.305: Q1.5 Q1.6 Q1.1 ; Q1.1 92.75,13.07 DS1.C ; Q1.1 Q1.2
UNNAMED_5_DIOLED_I70_P: length 2.1
  TOP w0.305: R26.1 94.36,14.8 DS1.A
UNNAMED_5_DIOSCHOTTKY3PV10_I6_1: length 12.4
  TOP w0.305: D6.2 8.51,3.05 8.51,6.52 R30.1 9.55,7.56 R32.1 9.52,9.67 U10.4
UNNAMED_5_DIOSCHOTTKY3PV10_I60_: length 7.8
  TOP w0.305: D4.2 73.19,34.15 R24.2 72.57,28.14 U8.4
UNNAMED_5_DIOSCHOTTKY3PV10_I64_: length 12
  TOP w0.305: D6.1 5.08,1.52 3.45,3.15 3.45,6.38 2.25,7.58 R29.1 R31.1 2.24,9.67 U10.1
UNNAMED_5_RES_I68_N2: length 48.5
  TOP w0.305: R36.2 v1(49.73,16.5) ; U10.6 5.89,14.85 S2.2 S2.1 v1(16.64,14.87)
  BOTTOM w0.305: v1(49.73,16.5) 48.11,14.87 v1(16.64,14.87)
UNNAMED_7_CN10P_I1_N4: length 4
  TOP w0.305: P6.4 61.95,46.83 R33.2
UNNAMED_7_CN10P_I1_N5: length 4
  TOP w0.305: R34.2 59.41,46.81 P6.5
UNNAMED_7_CN10P_I1_N6: length 4
  TOP w0.305: R35.2 P6.6
VH: length 104.2
  TOP w0.305: P2.3 P2.1 21.54,33.06 VH.1 ; P2.3 P2.5 20.96,23.7 R19_SPACER.1 14.56,26.62 U1.3 ; P2.3 22.83,25.53 25.63,25.53 27.06,24.09 27.06,18.68 29.85,15.9 44.83,15.9 53.14,24.21 55.55,24.21 58.46,21.3 72.43,21.3 73.48,22.35 73.48,24.23 73.05,24.66 C25.2 72.51,27.14 U8.2
VIO: length 36.6
  TOP w0.305: U1.23 11.92,43.52 11.68,43.28 ; U9.9 U9.10 84.99,28.92 ; U10.5 6.39,12.36 6.73,12.7 v1(7.01,12.7) ; U3.2 U3.1 57.85,14.79 ; 5.39,8.81 U10.2
  TOP w0.635: D6.3 v2(7.47,3.73) ; D1.3 v1(1.93,44.18) ; v2(59.11,13.67) C7.2 59.07,14.79 57.85,14.79 ; R11.2 v1(2.45,41.3) ; v2(79.71,28.93) C32.1 80.89,28.92 C33.1 84.99,28.92 ; 5.39,8.81 5.39,7.92 C35.2 7.18,7.91 C34.2 v1(8.17,7.92) ; v2(9.86,38.71) C19.1 9.87,39.89 C20.1 10.11,41.71 11.68,43.28 ; R15.2 v2(18.81,38.75) ; R29.2 v2(2.24,4.57) ; R30.2 v2(9.53,4.52) ; D3.3 v2(5.63,46.99)
  L3_PWR w0.635: TP2.1 3.39,36.44 ; TP2.1 2.06,35.11 ; TP2.1 4.72,35.11 ; TP2.1 3.39,33.77
VRS: length 18.2
  TOP w0.305: U8.5 70.25,28.64 69.92,28.96
  TOP w0.635: 69.92,28.96 VRS.1 65.75,31.61 64.24,30.1 64.24,26.9 63.27,25.93 R21.2 61.96,23.96 C24.2

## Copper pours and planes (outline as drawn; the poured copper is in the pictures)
+2.5V on L3_PWR: 84.3,23.88 84.3,18.67 88.21,18.67 88.21,13.31 84.3,13.31 84.3,8.38 91.82,8.38 91.82,23.88
+4.096V on L3_PWR: 42.88,41.27 90.83,41.27 90.83,24.23 84.1,24.21 84.1,18.42 87.71,18.42 87.71,14.53 77.9,14.53 77.9,25.48 87.73,25.48 87.73,36.58 54.46,36.58 54.46,14.38 11.33,14.38 11.33,50.34 16.66,50.34 16.66,45.19 14.2,45.19 14.2,18.38 16.66,18.38 42.88,18.41
+5V on L3_PWR: 0.71,0.3 0.71,52.81 97.03,52.81 97.03,0.3
+5V_ARD on L3_PWR: 63.98,11.2 63.98,0.3 70.97,0.3 70.97,11.2
AGND on TOP: 0.71,22.17 0.71,52.81 31.29,52.81 31.29,28.6 26.29,28.6 26.29,22.17 ; 6 cut-outs
AGND on BOTTOM: 0.71,22.17 0.71,52.81 31.29,52.81 31.29,28.6 25.96,28.6 25.96,22.17 ; 3 cut-outs
AGND on L2_GND: 0.71,0.25 0.71,52.81 97.03,52.81 97.03,0.25 ; 1 cut-out
VIO on L3_PWR: 78.23,32.64 78.23,27.99 83.24,27.99 83.24,36.22 54.76,36.22 54.76,14.1 11.02,14.07 11.02,50.55 23.42,50.55 23.42,40.18 17.27,40.18 17.27,34.04 37.16,34.04 37.16,52.81 0.74,52.81 0.74,0.33 63.78,0.3 63.78,15.62 58.78,15.62 58.78,32.64

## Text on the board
BOTTOM: 08-043603 REV B Z
Ref Des/Silkscreen Bottom: DIGI1 | POWER | DIGI0 | ANALOG
User.Comments: CR_PHOTODIODE_2 | CR_PHOTODIODE_3 | 5.    DO NOT CUT THE EXCESS PINS OF THE FOLLOWING CONNECTORS: | 1  E006383 CONN-PCB BERG HDR       TSW-103-08-G-D CNSAMTEC2X3H330LD36 | M000389 TO PINS 5 AND 6 | A.      P3 | B.      P4 | C.      P5 | D.      P6 | E.      P7
Ref Des/Silkscreen Top: 1 | A0 | A1 | A2 | A3 | A4 | A5 | 5V | RH | RCAL2 | RCAL1 | AGND | EVAL-CN0395-ARDZ | RS | SCL | SDA | AREF | GND | 13 | IOREF | 12 | RESET | 11 | 3.3V | 10 | 9 | 8 | 7 | VIN | 6 | 5 | 4 | 3 | 2 | 0
PAGE_OUTLINE: R. MACDONALD | J. KEANE | R. AMPARO | NA | R. AMARILLE | G. CELEDONIO | D. EDRIAL | 03AUG16 | B | AS PER ECR-066984 | 26JAN17 | CUSTOMER EVALUATION Z
DIMENSION: (REF) | DIA MAX
User.15: RoHS COMPLIANT | PER IPC-4552 LATEST REVISION | ENIG (ELECTROLESS NICKEL IMMERSION GOLD)
User.17: L2 GND | 08-      -07
User.18: L3 PWR | 08-      -08
User.45: FIGURE | SIZE | 12.0 | 20.0 | 37.0 | 40.0 | 45.0 | 50.0 | 63.0 | 65.0 | 125.0 | PLATED | NON-PLATED | FINISHED HOLES IN MILS | ALL UNITS ARE IN MILS | QTY | 94 | 53 | 4 | 3 | 44 | 10 | TOLERANCE/NOTES
